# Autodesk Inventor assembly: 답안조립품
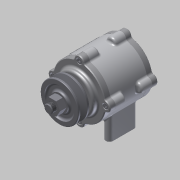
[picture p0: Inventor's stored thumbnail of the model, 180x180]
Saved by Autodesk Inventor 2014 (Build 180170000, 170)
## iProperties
Created: 2015-03
Part Number: 답안조립품
Document SubType Name: Assembly
Designer: MYHOME
Author: MYHOME
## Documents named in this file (11)
- C:\Documents and Settings\MYHOME\바탕 화면\450306V1021\답안조립품.iam
- C:\Documents and Settings\MYHOME\바탕 화면\450306V1021\본체.ipt
- C:\Documents and Settings\MYHOME\바탕 화면\450306V1021\커버.ipt
- C:\Documents and Settings\MYHOME\바탕 화면\450306V1021\커버2.ipt
- C:\Documents and Settings\MYHOME\바탕 화면\450306V1021\M 4 x 12.ipt
- C:\Documents and Settings\MYHOME\바탕 화면\450306V1021\베어링 6204.ipt
- C:\Documents and Settings\MYHOME\바탕 화면\450306V1021\축.ipt
- C:\Documents and Settings\MYHOME\바탕 화면\450306V1021\오일실.ipt
- C:\Documents and Settings\MYHOME\바탕 화면\450306V1021\키(4 x 4 x 12).ipt
- C:\Documents and Settings\MYHOME\바탕 화면\450306V1021\V벨트풀리.ipt
- C:\Documents and Settings\MYHOME\바탕 화면\450306V1021\너트 M12x1.25.ipt
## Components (14 placed, 6 different names)
1. KS B 2023 6204 - 20 x 47 x 14:1 — 각도:1
2. KS B 2023 6204 - 20 x 47 x 14:2 — 각도:2
3. KS B 2804 D D - 20 32 8:1
4. KS B 1311 (I) 4 x 4 x 12:1
5. 그루브 풀리1:1
6. KS B 1012 클래스 1 일반 - 미터 M12x1.25:1 — 각도:3
7. KS B 1003 - 미터 M 4 x 12:1
8. KS B 1003 - 미터 M 4 x 12:2
9. KS B 1003 - 미터 M 4 x 12:3
10. KS B 1003 - 미터 M 4 x 12:4
11. KS B 1003 - 미터 M 4 x 12:5
12. KS B 1003 - 미터 M 4 x 12:6
13. KS B 1003 - 미터 M 4 x 12:7
14. KS B 1003 - 미터 M 4 x 12:8
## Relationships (3: Angle 3)
- 각도:1 [Angle]: KS B 2023 6204 - 20 x 47 x 14:1
- 각도:2 [Angle]: KS B 2023 6204 - 20 x 47 x 14:2
- 각도:3 [Angle]: KS B 1012 클래스 1 일반 - 미터 M12x1.25:1
